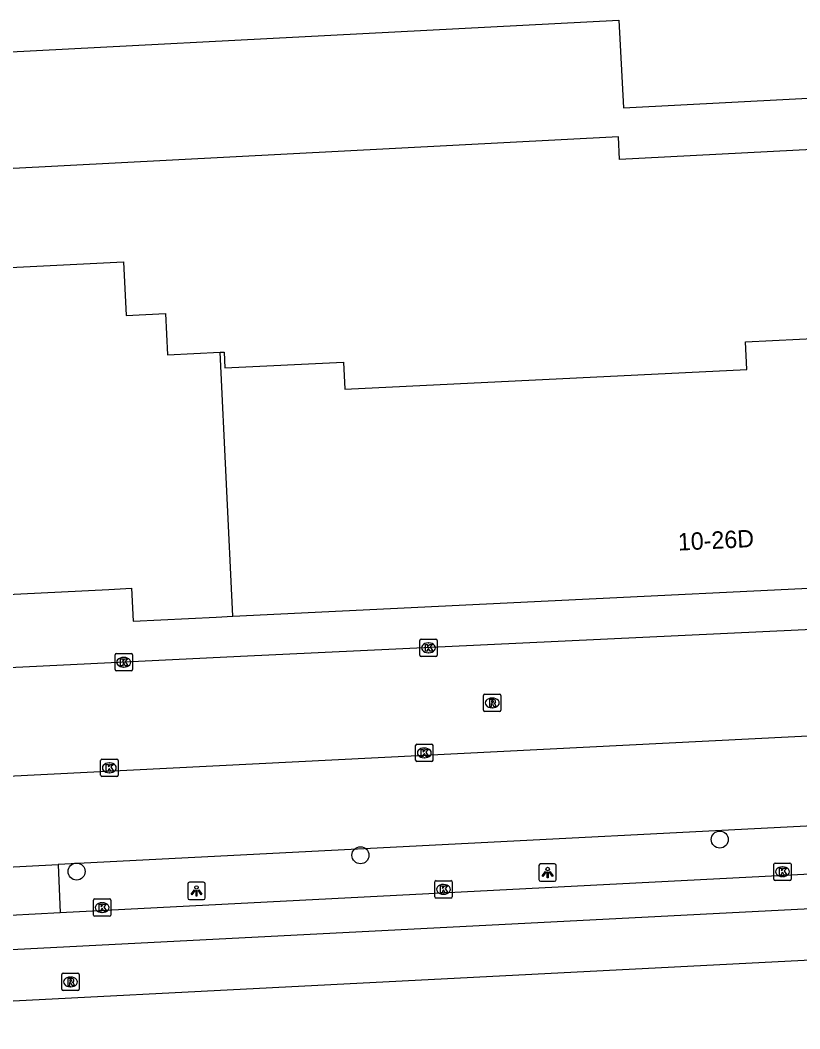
# Model space of a CAD drawing. Extents: x 161084 to 161928, y 385355 to 386522.
# Drawn here: x 161434.1 to 161479, y 385360.1 to 385418.1 of the extents above; entities that cross this region are included whole.
import ezdxf

# ---------------------------------------------------------------- set-up
doc = ezdxf.new("R2010")
doc.units = 0
for name, color, linetype in [('IMGEO_Boom', 7, 'Continuous'), ('IMGEO_Kolk', 7, 'Continuous'), ('IMGEO_Lichtpunt', 7, 'Continuous'), ('IMGEO_Pand', 7, 'Continuous'), ('IMGEO_Pand_nummerreeks', 7, 'Continuous'), ('IMGEO_Parkeervlak_open', 7, 'Continuous'), ('IMGEO_Rijbaan_lokaal_gesloten', 7, 'Continuous'), ('IMGEO_Rijbaan_lokaal_open', 7, 'Continuous'), ('IMGEO_Rioolput', 7, 'Continuous'), ('IMGEO_Voetpad_open', 7, 'Continuous')]:
    doc.layers.add(name, color=color, linetype=linetype)

msp = doc.modelspace()

# ---------------------------------------------------------------- linework, layer by layer
at = {"layer": 'IMGEO_Boom'}
for centre in [(161474.347, 385370.971), (161453.658, 385370.068), (161437.312, 385369.131)]:
    msp.add_circle(centre, 0.489, dxfattribs=at)
at = {"layer": 'IMGEO_Kolk'}
for p, q in [((161457.072, 385381.586), (161457.072, 385382.438)), ((161457.147, 385382.512), (161457.999, 385382.512)), ((161457.56, 385382.292), (161457.585, 385382.292)), ((161458.073, 385382.438), (161458.073, 385381.586)), ((161439.522, 385380.756), (161439.522, 385381.608)), ((161439.597, 385381.682), (161440.449, 385381.682)), ((161440.01, 385381.462), (161440.035, 385381.462)), ((161440.523, 385381.608), (161440.523, 385380.756)), ((161457.999, 385381.512), (161457.147, 385381.512)), ((161457.583, 385381.732), (161457.558, 385381.732)), ((161440.033, 385380.902), (161440.008, 385380.902)), ((161440.449, 385380.682), (161439.597, 385380.682)), ((161456.833, 385375.538), (161456.833, 385376.39)), ((161456.908, 385376.464), (161457.76, 385376.464)), ((161457.321, 385376.244), (161457.346, 385376.244)), ((161457.834, 385376.39), (161457.834, 385375.538)), ((161438.771, 385375.603), (161439.623, 385375.603)), ((161457.344, 385375.684), (161457.319, 385375.684)), ((161438.696, 385374.677), (161438.696, 385375.529)), ((161439.184, 385375.383), (161439.209, 385375.383)), ((161439.697, 385375.529), (161439.697, 385374.677)), ((161457.76, 385375.464), (161456.908, 385375.464)), ((161439.623, 385374.603), (161438.771, 385374.603)), ((161439.207, 385374.823), (161439.182, 385374.823)), ((161477.464, 385368.696), (161477.464, 385369.548)), ((161477.539, 385369.622), (161478.391, 385369.622)), ((161477.952, 385369.402), (161477.977, 385369.402)), ((161478.465, 385369.548), (161478.465, 385368.696)), ((161478.391, 385368.622), (161477.539, 385368.622)), ((161477.975, 385368.842), (161477.95, 385368.842)), ((161457.936, 385367.681), (161457.936, 385368.533)), ((161458.011, 385368.607), (161458.863, 385368.607)), ((161458.424, 385368.387), (161458.449, 385368.387)), ((161458.937, 385368.533), (161458.937, 385367.681)), ((161438.281, 385366.63), (161438.281, 385367.482)), ((161438.356, 385367.556), (161439.208, 385367.556)), ((161439.282, 385367.482), (161439.282, 385366.63)), ((161458.863, 385367.607), (161458.011, 385367.607)), ((161458.447, 385367.827), (161458.422, 385367.827)), ((161438.769, 385367.336), (161438.794, 385367.336)), ((161439.208, 385366.556), (161438.356, 385366.556)), ((161438.792, 385366.776), (161438.767, 385366.776))]:
    msp.add_line(p, q, dxfattribs=at)
for points in [[(161457.072, 385381.586), (161457.072, 385382.438)], [(161457.147, 385382.512), (161457.999, 385382.512)], [(161457.393, 385382.212), (161457.516, 385382.212), (161457.516, 385382.061), (161457.646, 385382.212), (161457.81, 385382.212), (161457.664, 385382.061), (161457.817, 385381.812), (161457.665, 385381.812), (161457.58, 385381.976), (161457.516, 385381.909), (161457.516, 385381.812), (161457.393, 385381.812), (161457.393, 385382.212)], [(161458.073, 385382.438), (161458.073, 385381.586)], [(161439.522, 385380.756), (161439.522, 385381.608)], [(161439.597, 385381.682), (161440.449, 385381.682)], [(161440.523, 385381.608), (161440.523, 385380.756)], [(161457.999, 385381.512), (161457.147, 385381.512)], [(161439.843, 385381.382), (161439.966, 385381.382), (161439.966, 385381.231), (161440.096, 385381.382), (161440.26, 385381.382), (161440.114, 385381.231), (161440.267, 385380.982), (161440.115, 385380.982), (161440.03, 385381.146), (161439.966, 385381.079), (161439.966, 385380.982), (161439.843, 385380.982), (161439.843, 385381.382)], [(161440.449, 385380.682), (161439.597, 385380.682)], [(161456.833, 385375.538), (161456.833, 385376.39)], [(161456.908, 385376.464), (161457.76, 385376.464)], [(161457.154, 385376.164), (161457.277, 385376.164), (161457.277, 385376.013), (161457.407, 385376.164), (161457.571, 385376.164), (161457.425, 385376.013), (161457.578, 385375.764), (161457.426, 385375.764), (161457.341, 385375.928), (161457.277, 385375.861), (161457.277, 385375.764), (161457.154, 385375.764), (161457.154, 385376.164)], [(161457.834, 385376.39), (161457.834, 385375.538)], [(161438.771, 385375.603), (161439.623, 385375.603)], [(161438.696, 385374.677), (161438.696, 385375.529)], [(161439.017, 385375.303), (161439.14, 385375.303), (161439.14, 385375.152), (161439.27, 385375.303), (161439.434, 385375.303), (161439.288, 385375.152), (161439.441, 385374.903), (161439.289, 385374.903), (161439.204, 385375.067), (161439.14, 385375), (161439.14, 385374.903), (161439.017, 385374.903), (161439.017, 385375.303)], [(161439.697, 385375.529), (161439.697, 385374.677)], [(161457.76, 385375.464), (161456.908, 385375.464)], [(161439.623, 385374.603), (161438.771, 385374.603)], [(161477.464, 385368.696), (161477.464, 385369.548)], [(161477.539, 385369.622), (161478.391, 385369.622)], [(161477.785, 385369.322), (161477.908, 385369.322), (161477.908, 385369.171), (161478.038, 385369.322), (161478.202, 385369.322), (161478.056, 385369.171), (161478.209, 385368.922), (161478.057, 385368.922), (161477.972, 385369.086), (161477.908, 385369.019), (161477.908, 385368.922), (161477.785, 385368.922), (161477.785, 385369.322)], [(161478.465, 385369.548), (161478.465, 385368.696)], [(161478.391, 385368.622), (161477.539, 385368.622)], [(161457.936, 385367.681), (161457.936, 385368.533)], [(161458.011, 385368.607), (161458.863, 385368.607)], [(161458.257, 385368.307), (161458.38, 385368.307), (161458.38, 385368.156), (161458.51, 385368.307), (161458.674, 385368.307), (161458.528, 385368.156), (161458.681, 385367.907), (161458.529, 385367.907), (161458.444, 385368.071), (161458.38, 385368.004), (161458.38, 385367.907), (161458.257, 385367.907), (161458.257, 385368.307)], [(161458.937, 385368.533), (161458.937, 385367.681)], [(161438.281, 385366.63), (161438.281, 385367.482)], [(161438.356, 385367.556), (161439.208, 385367.556)], [(161439.282, 385367.482), (161439.282, 385366.63)], [(161458.863, 385367.607), (161458.011, 385367.607)], [(161438.602, 385367.256), (161438.725, 385367.256), (161438.725, 385367.105), (161438.855, 385367.256), (161439.019, 385367.256), (161438.873, 385367.105), (161439.026, 385366.856), (161438.874, 385366.856), (161438.789, 385367.02), (161438.725, 385366.953), (161438.725, 385366.856), (161438.602, 385366.856), (161438.602, 385367.256)], [(161439.208, 385366.556), (161438.356, 385366.556)]]:
    msp.add_lwpolyline(points, dxfattribs=at)
for centre, start, end in [((161457.149, 385382.436), 91.55205, 178.44795), ((161457.149, 385382.436), 91.55205, 178.44795), ((161457.997, 385382.436), 1.55205, 88.44795), ((161457.997, 385382.436), 1.55205, 88.44795), ((161439.599, 385381.606), 91.55205, 178.44795), ((161439.599, 385381.606), 91.55205, 178.44795), ((161440.447, 385381.606), 1.55205, 88.44795), ((161440.447, 385381.606), 1.55205, 88.44795), ((161457.149, 385381.588), 181.55205, 268.44795), ((161457.149, 385381.588), 181.55205, 268.44795), ((161457.997, 385381.588), 271.55205, 358.44795), ((161457.997, 385381.588), 271.55205, 358.44795), ((161439.599, 385380.758), 181.55205, 268.44795), ((161439.599, 385380.758), 181.55205, 268.44795), ((161440.447, 385380.758), 271.55205, 358.44795), ((161440.447, 385380.758), 271.55205, 358.44795), ((161456.91, 385376.388), 91.55205, 178.44795), ((161456.91, 385376.388), 91.55205, 178.44795), ((161457.758, 385376.388), 1.55205, 88.44795), ((161457.758, 385376.388), 1.55205, 88.44795), ((161438.773, 385375.527), 91.55205, 178.44795), ((161438.773, 385375.527), 91.55205, 178.44795), ((161439.621, 385375.527), 1.55205, 88.44795), ((161439.621, 385375.527), 1.55205, 88.44795), ((161456.91, 385375.54), 181.55205, 268.44795), ((161456.91, 385375.54), 181.55205, 268.44795), ((161457.758, 385375.54), 271.55205, 358.44795), ((161457.758, 385375.54), 271.55205, 358.44795), ((161438.773, 385374.679), 181.55205, 268.44795), ((161438.773, 385374.679), 181.55205, 268.44795), ((161439.621, 385374.679), 271.55205, 358.44795), ((161439.621, 385374.679), 271.55205, 358.44795), ((161477.541, 385369.546), 91.55205, 178.44795), ((161477.541, 385369.546), 91.55205, 178.44795), ((161478.389, 385369.546), 1.55205, 88.44795), ((161478.389, 385369.546), 1.55205, 88.44795), ((161477.541, 385368.698), 181.55205, 268.44795), ((161477.541, 385368.698), 181.55205, 268.44795), ((161478.389, 385368.698), 271.55205, 358.44795), ((161478.389, 385368.698), 271.55205, 358.44795), ((161458.013, 385368.531), 91.55205, 178.44795), ((161458.013, 385368.531), 91.55205, 178.44795), ((161458.861, 385368.531), 1.55205, 88.44795), ((161458.861, 385368.531), 1.55205, 88.44795), ((161438.358, 385367.48), 91.55205, 178.44795), ((161438.358, 385367.48), 91.55205, 178.44795), ((161439.206, 385367.48), 1.55205, 88.44795), ((161439.206, 385367.48), 1.55205, 88.44795), ((161458.013, 385367.683), 181.55205, 268.44795), ((161458.013, 385367.683), 181.55205, 268.44795), ((161458.861, 385367.683), 271.55205, 358.44795), ((161458.861, 385367.683), 271.55205, 358.44795), ((161438.358, 385366.632), 181.55205, 268.44795), ((161438.358, 385366.632), 181.55205, 268.44795), ((161439.206, 385366.632), 271.55205, 358.44795), ((161439.206, 385366.632), 271.55205, 358.44795)]:
    msp.add_arc(centre, 0.0765, start, end, dxfattribs=at)
for centre, major_axis, ratio, start_param, end_param in [((161457.559, 385382.012), (-0.387, 0.002), 0.722429, 4.712389, 7.853982), ((161457.584, 385382.012), (-0.39, 0.002), 0.717154, 1.570796, 4.712389), ((161440.009, 385381.182), (-0.387, 0.002), 0.722429, 4.712389, 7.853982), ((161440.034, 385381.182), (-0.39, 0.002), 0.717154, 1.570796, 4.712389), ((161457.32, 385375.964), (-0.387, 0.002), 0.722429, 4.712389, 7.853982), ((161457.345, 385375.964), (-0.39, 0.002), 0.717154, 1.570796, 4.712389), ((161439.183, 385375.103), (-0.387, 0.002), 0.722429, 4.712389, 7.853982), ((161439.208, 385375.103), (-0.39, 0.002), 0.717154, 1.570796, 4.712389), ((161477.951, 385369.122), (-0.387, 0.002), 0.722429, 4.712389, 7.853982), ((161477.976, 385369.122), (-0.39, 0.002), 0.717154, 1.570796, 4.712389), ((161458.423, 385368.107), (-0.387, 0.002), 0.722429, 4.712389, 7.853982), ((161458.448, 385368.107), (-0.39, 0.002), 0.717154, 1.570796, 4.712389), ((161438.768, 385367.056), (-0.387, 0.002), 0.722429, 4.712389, 7.853982), ((161438.793, 385367.056), (-0.39, 0.002), 0.717154, 1.570796, 4.712389)]:
    msp.add_ellipse(centre, major_axis=major_axis, ratio=ratio, start_param=start_param, end_param=end_param, dxfattribs=at)
at = {"layer": 'IMGEO_Lichtpunt'}
for p, q in [((161463.937, 385369.479), (161463.937, 385368.672)), ((161463.937, 385369.479), (161463.937, 385368.672)), ((161464.839, 385369.574), (161464.031, 385369.574)), ((161464.839, 385369.574), (161464.031, 385369.574)), ((161464.933, 385368.672), (161464.933, 385369.479)), ((161464.933, 385368.672), (161464.933, 385369.479)), ((161443.717, 385368.421), (161443.717, 385367.614)), ((161443.717, 385368.421), (161443.717, 385367.614)), ((161444.619, 385368.516), (161443.811, 385368.516)), ((161444.619, 385368.516), (161443.811, 385368.516)), ((161444.713, 385367.614), (161444.713, 385368.421)), ((161444.713, 385367.614), (161444.713, 385368.421)), ((161464.031, 385368.578), (161464.839, 385368.578)), ((161464.031, 385368.578), (161464.839, 385368.578)), ((161443.811, 385367.52), (161444.619, 385367.52)), ((161443.811, 385367.52), (161444.619, 385367.52))]:
    msp.add_line(p, q, dxfattribs=at)
for points in [[(161464.311, 385369.143), (161464.35, 385369.115), (161464.162, 385368.853), (161464.124, 385368.88), (161464.311, 385369.143)], [(161464.413, 385369.095), (161464.46, 385369.095), (161464.46, 385368.773), (161464.413, 385368.773), (161464.413, 385369.095)], [(161464.523, 385369.115), (161464.561, 385369.142), (161464.748, 385368.88), (161464.709, 385368.852), (161464.523, 385369.115)], [(161444.091, 385368.085), (161444.13, 385368.057), (161443.942, 385367.795), (161443.904, 385367.822), (161444.091, 385368.085)], [(161444.193, 385368.037), (161444.24, 385368.037), (161444.24, 385367.715), (161444.193, 385367.715), (161444.193, 385368.037)], [(161444.303, 385368.057), (161444.341, 385368.084), (161444.528, 385367.822), (161444.489, 385367.794), (161444.303, 385368.057)]]:
    msp.add_lwpolyline(points, dxfattribs=at)
for centre in [(161464.436, 385369.277), (161444.216, 385368.219)]:
    msp.add_circle(centre, 0.0994, dxfattribs=at)
for centre, start, end in [((161464.031, 385369.479), 90, 180), ((161464.031, 385369.479), 90, 180), ((161464.839, 385369.479), 0, 90), ((161464.839, 385369.479), 0, 90), ((161464.031, 385368.672), 180, 270), ((161464.031, 385368.672), 180, 270), ((161464.839, 385368.672), 270, 0), ((161464.839, 385368.672), 270, 360), ((161443.811, 385368.421), 90, 180), ((161443.811, 385368.421), 90, 180), ((161444.619, 385368.421), 0, 90), ((161444.619, 385368.421), 0, 90), ((161443.811, 385367.614), 180, 270), ((161443.811, 385367.614), 180, 270), ((161444.619, 385367.614), 270, 0), ((161444.619, 385367.614), 270, 360)]:
    msp.add_arc(centre, 0.0946, start, end, dxfattribs=at)
at = {"layer": 'IMGEO_Pand'}
for points in [[(161507.406, 385414.52), (161504.762, 385414.382), (161504.886, 385412.015), (161500, 385411.76), (161468.584, 385410.119), (161468.516, 385411.422), (161423.742, 385409.085), (161418.748, 385408.824), (161418.397, 385415.54), (161468.535, 385418.145), (161468.809, 385413.105), (161500, 385414.726), (161507.377, 385415.11)], [(161405.035, 385404.251), (161418.379, 385404.916), (161418.467, 385403.152), (161423.461, 385403.401), (161440.017, 385404.225), (161440.171, 385401.137), (161442.426, 385401.249), (161442.544, 385398.875), (161445.572, 385399.025)], [(161445.572, 385399.025), (161445.807, 385399.037), (161445.852, 385398.132), (161452.676, 385398.466), (161452.752, 385396.902), (161475.903, 385398.035), (161475.825, 385399.632), (161488.262, 385400.24), (161488.339, 385398.664), (161499.846, 385399.227), (161499.769, 385400.786), (161500, 385400.797), (161508.057, 385401.191)], [(161446.313, 385383.833), (161445.572, 385399.025)], [(161446.313, 385383.833), (161500, 385386.452), (161504.075, 385386.651)], [(161420.925, 385382.589), (161424.817, 385382.783), (161424.724, 385384.657), (161439.175, 385385.376), (161440.478, 385385.441), (161440.573, 385383.548), (161445.352, 385383.786), (161446.313, 385383.833)]]:
    msp.add_lwpolyline(points, dxfattribs=at)
at = {"layer": 'IMGEO_Parkeervlak_open'}
msp.add_lwpolyline([(161611.642, 385381.949), (161611.734, 385378.546), (161536.947, 385374.696), (161499.966, 385372.793), (161436.244, 385369.529)], dxfattribs=at)
at = {"layer": 'IMGEO_Rijbaan_lokaal_gesloten'}
for points in [[(161612.776, 385375.763), (161606.577, 385375.444), (161537.172, 385371.897), (161505.307, 385370.314), (161500.052, 385370.04), (161436.355, 385366.757)], [(161622.181, 385375.572), (161615.993, 385374.116), (161611.842, 385373.703), (161604.686, 385373.29), (161508.768, 385368.474), (161402.097, 385363.009)], [(161402.264, 385360.078), (161479.217, 385364.029), (161505.666, 385365.356), (161523.978, 385366.275), (161544.274, 385367.294), (161580.676, 385369.12), (161602.822, 385370.279), (161621.627, 385370.918)], [(161436.355, 385366.757), (161401.799, 385364.905)]]:
    msp.add_lwpolyline(points, dxfattribs=at)
at = {"layer": 'IMGEO_Rijbaan_lokaal_open'}
for points in [[(161503.842, 385384.114), (161501.355, 385384.05), (161500, 385384.027), (161446.746, 385381.511), (161422.04, 385380.3), (161408.687, 385379.455)], [(161409.084, 385373.337), (161409.328, 385373.422), (161500, 385377.979), (161536.651, 385379.888), (161613.107, 385383.789)]]:
    msp.add_lwpolyline(points, dxfattribs=at)
at = {"layer": 'IMGEO_Rioolput'}
for p, q in [((161460.747, 385378.414), (161460.747, 385379.266)), ((161460.822, 385379.34), (161461.674, 385379.34)), ((161461.235, 385379.12), (161461.26, 385379.12)), ((161461.748, 385379.266), (161461.748, 385378.414)), ((161461.258, 385378.56), (161461.233, 385378.56)), ((161461.674, 385378.34), (161460.822, 385378.34)), ((161436.46, 385362.352), (161436.46, 385363.204)), ((161436.535, 385363.278), (161437.387, 385363.278)), ((161436.948, 385363.058), (161436.973, 385363.058)), ((161437.461, 385363.204), (161437.461, 385362.352)), ((161437.387, 385362.278), (161436.535, 385362.278)), ((161436.971, 385362.498), (161436.946, 385362.498))]:
    msp.add_line(p, q, dxfattribs=at)
for points in [[(161460.747, 385378.414), (161460.747, 385379.266)], [(161460.822, 385379.34), (161461.674, 385379.34)], [(161461.748, 385379.266), (161461.748, 385378.414)], [(161461.336, 385379.038), (161461.084, 385379.04), (161461.084, 385378.64)], [(161461.084, 385378.64), (161461.208, 385378.64), (161461.208, 385378.802), (161461.219, 385378.802)], [(161461.262, 385378.959), (161461.208, 385378.959), (161461.208, 385378.878)], [(161461.208, 385378.878), (161461.26, 385378.878)], [(161461.266, 385378.773), (161461.337, 385378.64), (161461.477, 385378.64), (161461.412, 385378.766)], [(161461.674, 385378.34), (161460.822, 385378.34)], [(161436.46, 385362.352), (161436.46, 385363.204)], [(161436.535, 385363.278), (161437.387, 385363.278)], [(161437.049, 385362.976), (161436.797, 385362.978), (161436.797, 385362.578)], [(161436.975, 385362.897), (161436.921, 385362.897), (161436.921, 385362.816)], [(161436.921, 385362.816), (161436.973, 385362.816)], [(161437.461, 385363.204), (161437.461, 385362.352)], [(161437.387, 385362.278), (161436.535, 385362.278)], [(161436.797, 385362.578), (161436.921, 385362.578), (161436.921, 385362.74), (161436.932, 385362.74)], [(161436.979, 385362.711), (161437.05, 385362.578), (161437.19, 385362.578), (161437.125, 385362.704)]]:
    msp.add_lwpolyline(points, dxfattribs=at)
for centre, radius, start, end in [((161460.824, 385379.264), 0.0765, 91.55205, 178.44795), ((161460.824, 385379.264), 0.0765, 91.55205, 178.44795), ((161461.672, 385379.264), 0.0765, 1.55205, 88.44795), ((161461.672, 385379.264), 0.0765, 1.55205, 88.44795), ((161461.218, 385378.749), 0.0533, 26.02933, 88.69889), ((161461.244, 385379.067), 0.19, 274.7715, 282.96867), ((161461.268, 385378.863), 0.0964, 77.00612, 93.18647), ((161461.282, 385378.92), 0.0378, 276.66336, 79.67722), ((161461.335, 385378.928), 0.109, 350.36119, 89.41601), ((161461.333, 385378.928), 0.112, 277.58423, 350.98172), ((161461.317, 385378.713), 0.108, 29.51342, 73.79051), ((161460.824, 385378.416), 0.0765, 181.55205, 268.44795), ((161460.824, 385378.416), 0.0765, 181.55205, 268.44795), ((161461.672, 385378.416), 0.0765, 271.55205, 358.44795), ((161461.672, 385378.416), 0.0765, 271.55205, 358.44795), ((161436.537, 385363.202), 0.0765, 91.55205, 178.44795), ((161436.537, 385363.202), 0.0765, 91.55205, 178.44795), ((161436.957, 385363.005), 0.19, 274.7715, 282.96867), ((161436.981, 385362.801), 0.0964, 77.00612, 93.18647), ((161436.995, 385362.858), 0.0378, 276.66336, 79.67722), ((161437.048, 385362.866), 0.109, 350.36119, 89.41601), ((161437.046, 385362.866), 0.112, 277.58423, 350.98172), ((161437.385, 385363.202), 0.0765, 1.55205, 88.44795), ((161437.385, 385363.202), 0.0765, 1.55205, 88.44795), ((161436.537, 385362.354), 0.0765, 181.55205, 268.44795), ((161436.537, 385362.354), 0.0765, 181.55205, 268.44795), ((161436.931, 385362.687), 0.0533, 26.02933, 88.69889), ((161437.03, 385362.651), 0.108, 29.51342, 73.79051), ((161437.385, 385362.354), 0.0765, 271.55205, 358.44795), ((161437.385, 385362.354), 0.0765, 271.55205, 358.44795)]:
    msp.add_arc(centre, radius, start, end, dxfattribs=at)
for centre, major_axis, ratio, start_param, end_param in [((161461.234, 385378.84), (-0.387, 0.002), 0.722429, 4.712389, 7.853982), ((161461.259, 385378.84), (-0.39, 0.002), 0.717154, 1.570796, 4.712389), ((161436.947, 385362.778), (-0.387, 0.002), 0.722429, 4.712389, 7.853982), ((161436.972, 385362.778), (-0.39, 0.002), 0.717154, 1.570796, 4.712389)]:
    msp.add_ellipse(centre, major_axis=major_axis, ratio=ratio, start_param=start_param, end_param=end_param, dxfattribs=at)
at = {"layer": 'IMGEO_Voetpad_open'}
for points in [[(161411.152, 385368.227), (161436.244, 385369.529)], [(161436.244, 385369.529), (161436.355, 385366.757)]]:
    msp.add_lwpolyline(points, dxfattribs=at)

# ---------------------------------------------------------------- texts
at = {"layer": 'IMGEO_Pand_nummerreeks'}
msp.add_text('10-26D', height=1, rotation=2.79315, dxfattribs=at).set_placement((161471.96, 385387.607))

doc.saveas('drawing.dxf')
